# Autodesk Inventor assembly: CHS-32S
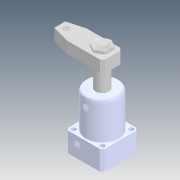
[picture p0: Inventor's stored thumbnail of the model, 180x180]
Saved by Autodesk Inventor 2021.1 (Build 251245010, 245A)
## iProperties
Created: 2020-02
Part Number: CHS-32S
Description: STEP AP214
Document SubType Name: Assembly
Designer: user
Title: chs-32s_asm.STEP
Revision Number: ÈÎºÎ
Sending System: SolidWorks 2016
Preprocessor: SwSTEP 2.0
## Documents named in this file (5)
- D:\Vault_2016\Projekty\Clamptek\Hydraulic\CHS\CHS-32\Inventor\CHS-32S\CHS-32S.iam
- D:\Vault_2016\Projekty\Clamptek\Hydraulic\CHS\CHS-32\Inventor\CHS-32S\CHS-32-03_1.ipt
- D:\Vault_2016\Projekty\Clamptek\Hydraulic\CHS\CHS-32\Inventor\CHS-32S\CHS-32S-02.ipt
- D:\Vault_2016\Projekty\Clamptek\Hydraulic\CHS\CHS-32\Inventor\CHS-32S\CHS-32S-01.ipt
- D:\Vault_2016\Projekty\Clamptek\Hydraulic\CHS\CHS-32\Inventor\CHS-32S\M16.ipt
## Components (4 placed, 4 different names)
1. CHS-32-03_1_1
2. CHS-32S-02_2
3. CHS-32S-01_3
4. M16_4
